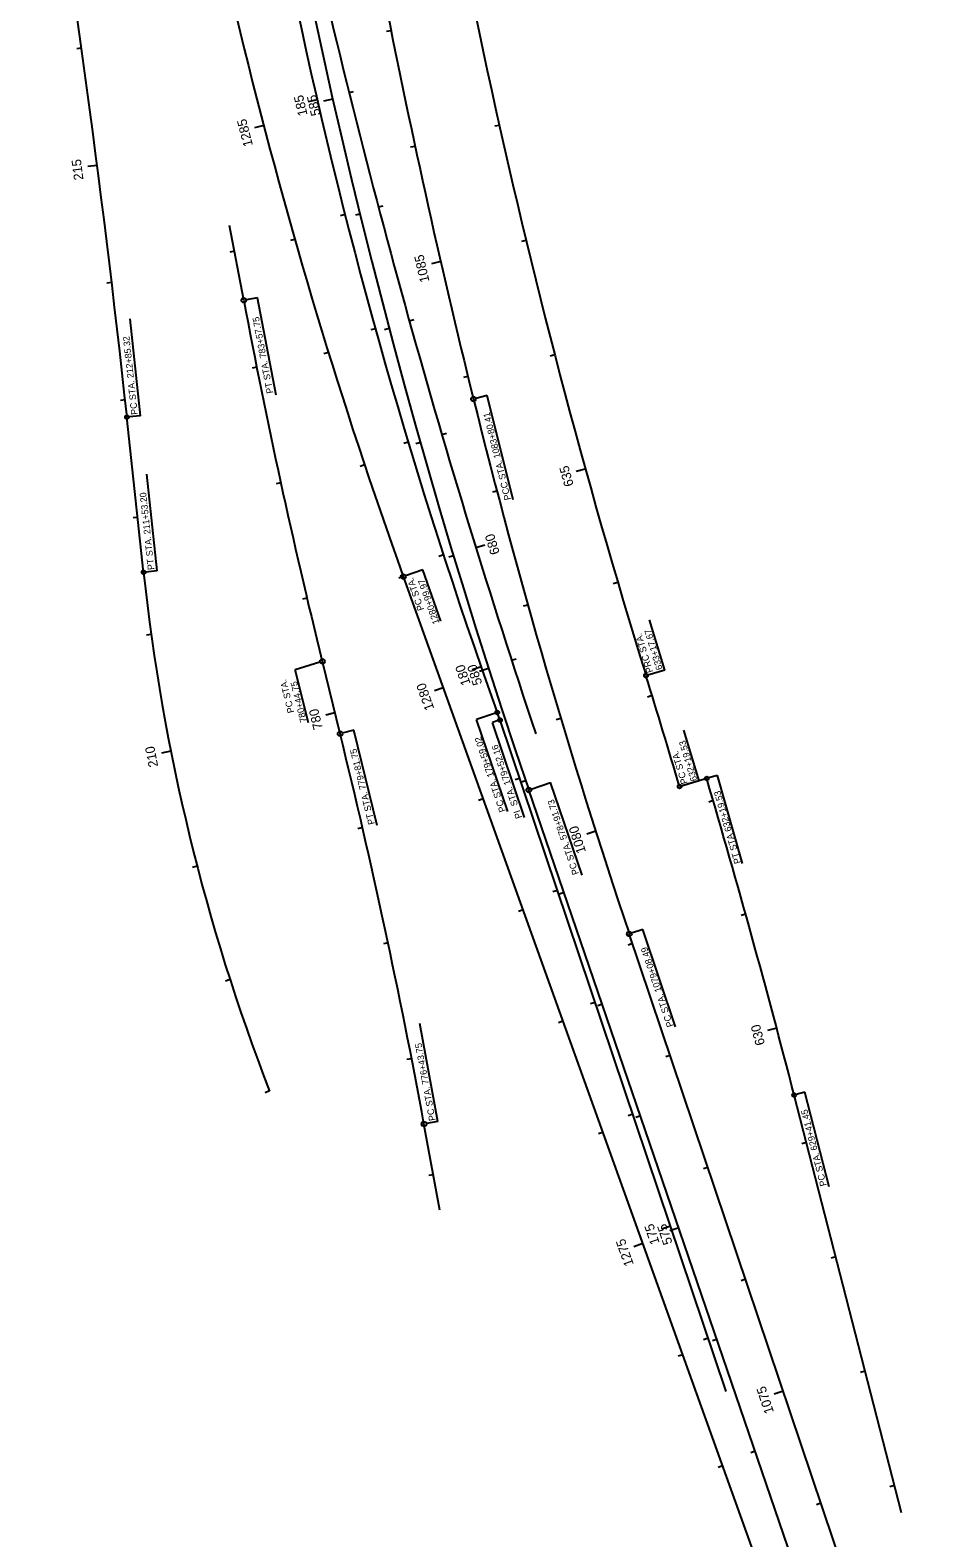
# Model space of a CAD drawing. Extents: x 919451 to 931682, y 583214 to 665619.
# Drawn here: x 928872 to 929643, y 633141 to 634418 of the extents above; entities that cross this region are included whole.
import ezdxf

# ---------------------------------------------------------------- set-up
doc = ezdxf.new("R2010")
doc.units = 0
for name, color, linetype in [('CLConst_dp', 7, 'Continuous'), ('ScratchEle_dp', 7, 'Continuous'), ('StationTicL_dp', 7, 'Continuous'), ('StationTicS_dp', 7, 'Continuous'), ('TextBLStation', 7, 'Continuous')]:
    doc.layers.add(name, color=color, linetype=linetype)

msp = doc.modelspace()

# ---------------------------------------------------------------- linework, layer by layer
at = {"layer": 'CLConst_dp'}
for p, q in [((929052.5, 634189), (929040.6, 634252.2)), ((928967.7, 633958.7), (928953.6, 634090.1)), ((929494.7, 633100.4), (929187.7, 633955.1)), ((929134.1, 633822), (929119.1, 633883.2)), ((929269.6, 633833.6), (929267.3, 633840)), ((929461.1, 633265), (929269.6, 633833.6)), ((929444.7, 633784.1), (929421.7, 633777.3)), ((929643, 632755.1), (929294, 633774.4)), ((929620.6, 632935.5), (929379.1, 633652.5)), ((929609.6, 633162.5), (929518.7, 633516.1)), ((929218.7, 633418.6), (929205.2, 633491.6))]:
    msp.add_line(p, q, dxfattribs=at)
for centre, radius, start, end in [((934714.8, 635630.2), 5729.6, 175.95543, 198.89818), ((935124, 635648.4), 6000, 187.10964, 197.22933), ((933402.4, 635469), 4478.4, 187.8142, 199.7579), ((936244.1, 635835), 7207.6, 188.19915, 193.88471), ((919061.7, 633026.1), 9949, 6.13885, 9.59073), ((936128.2, 636105.4), 7200, 192.63655, 198.49103), ((933581.1, 635389.5), 4583.7, 191.9832, 199.7579), ((934682.4, 635253.2), 5729.6, 190.7042, 193.8342), ((934799.6, 635477.9), 5719.6, 193.8847, 198.6121), ((930687.2, 634143.6), 1729.4, 186.1389, 201.1539), ((922119.5, 631615.5), 7615.4, 16.49098, 17.22933), ((923570.7, 632452), 5729.6, 10.4542, 13.8342), ((922119.5, 631615.5), 7639.4, 14.40537, 16.49098)]:
    msp.add_arc(centre, radius, start, end, dxfattribs=at)
at = {"layer": 'StationTicL_dp'}
for p, q in [((929064.3, 634191.2), (929054.5, 634189.4)), ((929079.9, 634108.8), (929064.3, 634191.2)), ((928965.1, 634091.3), (928956.3, 634173.3)), ((929258.8, 634108.3), (929249.1, 634105.9)), ((929280.6, 634020.1), (929258.8, 634108.3)), ((928965.1, 634091.3), (928955.2, 634090.2)), ((928979.3, 633959.8), (928970.5, 634041.8)), ((928979.3, 633959.8), (928969.3, 633958.7)), ((929204.3, 633960.8), (929189.6, 633955.7)), ((929219.4, 633917.3), (929204.3, 633960.8)), ((929409.1, 633875.9), (929396.2, 633918.5)), ((929117.1, 633882.7), (929096.2, 633876.2)), ((929107.3, 633831.3), (929096.2, 633876.2)), ((929409.1, 633875.9), (929394.7, 633871.6)), ((929265.8, 633839.5), (929249.8, 633834.1)), ((929276.1, 633756.1), (929249.8, 633834.1)), ((929268.1, 633833.1), (929263.3, 633831.5)), ((929290.4, 633751.2), (929263.3, 633831.5)), ((929145.8, 633824.9), (929136, 633822.5)), ((929165.6, 633744.4), (929145.8, 633824.9)), ((929438.2, 633782.1), (929425.2, 633825.1)), ((929295.9, 633775.1), (929312.3, 633780.7)), ((929339.1, 633702.4), (929312.3, 633780.7)), ((929438.2, 633782.1), (929423.2, 633777.7)), ((929453.7, 633786.7), (929446.2, 633784.6)), ((929475.1, 633712.1), (929453.7, 633786.7)), ((929390.5, 633656.3), (929381, 633653.1)), ((929418.3, 633573.8), (929390.5, 633656.3)), ((929217, 633493.8), (929201.7, 633576.7)), ((929527.8, 633518.5), (929520.3, 633516.6)), ((929548.4, 633438.4), (929527.8, 633518.5)), ((929217, 633493.8), (929207.2, 633492))]:
    msp.add_line(p, q, dxfattribs=at)
for centre, radius in [((929052.5, 634189), 2), ((929247.1, 634105.4), 2), ((928953.6, 634090.1), 1.6), ((928967.7, 633958.7), 1.6), ((929187.7, 633955.1), 2), ((929119.1, 633883.2), 2), ((929393.2, 633871.2), 1.6), ((929267.3, 633840), 1.6), ((929269.6, 633833.6), 1.6), ((929134.1, 633822), 2), ((929421.7, 633777.3), 1.6), ((929444.7, 633784.1), 1.6), ((929444.7, 633784.1), 1.6), ((929294, 633774.4), 2), ((929379.1, 633652.5), 2), ((929518.7, 633516.1), 1.6), ((929205.2, 633491.6), 2)]:
    msp.add_circle(centre, radius, dxfattribs=at)
at = {"layer": 'StationTicS_dp'}
for p, q in [((929114.8, 634358.8), (929107, 634357)), ((929127.9, 634359.3), (929120.1, 634357.5)), ((929069.5, 634337.1), (929061.7, 634335.1)), ((928928.4, 634303.2), (928920.4, 634302.2)), ((929219.4, 634221.7), (929211.6, 634219.9)), ((929341.8, 634046.1), (929334.1, 634044)), ((929249.2, 633979.6), (929256.8, 633982)), ((929253.6, 633878.7), (929246, 633876)), ((929259.9, 633877.2), (929252.3, 633874.7)), ((929221.5, 633861), (929214, 633858.3)), ((929129.8, 633839.7), (929122, 633837.8)), ((928990.8, 633807.3), (928983, 633805.7)), ((929350.6, 633739.4), (929343, 633737)), ((929504, 633572.7), (929496.2, 633570.7)), ((929413.9, 633405.1), (929406.3, 633402.5)), ((929420.9, 633403.8), (929413.3, 633401.2)), ((929390.5, 633390.4), (929383, 633387.7)), ((929509.5, 633265.3), (929501.9, 633262.8))]:
    msp.add_line(p, q, dxfattribs=at)
at = {"layer": 'TextBLStation'}
for p, q in [((929177.3, 634417.2), (929173.4, 634416.5)), ((928915, 634402.4), (928911.1, 634401.8)), ((929141.7, 634364.9), (929145.6, 634365.9)), ((929269, 634337.1), (929265.1, 634336.3)), ((929197.7, 634319.3), (929193.8, 634318.5)), ((929166.6, 634268), (929170.5, 634269)), ((929138.4, 634261.6), (929134.5, 634260.6)), ((929150.9, 634261.9), (929147.1, 634261)), ((929095.8, 634240.6), (929092, 634239.5)), ((929291.7, 634239.7), (929287.8, 634238.8)), ((929044.7, 634230.5), (929040.8, 634229.8)), ((928940.7, 634204), (928936.7, 634203.5)), ((929164, 634164.9), (929160.2, 634163.9)), ((929175.7, 634165.1), (929171.8, 634164)), ((929192.8, 634171.5), (929196.6, 634172.6)), ((929124.3, 634144.8), (929120.5, 634143.6)), ((929315.9, 634142.7), (929312.1, 634141.7)), ((929063.6, 634132.3), (929059.6, 634131.5)), ((929242.4, 634124.4), (929238.6, 634123.5)), ((928952, 634104.7), (928948.1, 634104.2)), ((929220.3, 634075.4), (929224.2, 634076.5)), ((929191.8, 634068.9), (929188, 634067.7)), ((929202.1, 634068.6), (929198.2, 634067.5)), ((929154.9, 634049.6), (929151.1, 634048.3)), ((929084, 634034.4), (929080.1, 634033.5)), ((929267, 634027.5), (929263.1, 634026.5)), ((928962.7, 634005.2), (928958.8, 634004.8)), ((929221.7, 633973.4), (929217.9, 633972.2)), ((929230.2, 633972.6), (929226.3, 633971.5)), ((929187.7, 633955.1), (929183.9, 633953.8)), ((929369.4, 633950), (929365.5, 633948.9)), ((929106.1, 633936.9), (929102.2, 633936)), ((929293.2, 633931), (929289.3, 633929.9)), ((928974.2, 633905.9), (928970.3, 633905.4)), ((929279.4, 633884.3), (929283.2, 633885.5)), ((929398.4, 633854.3), (929394.6, 633853.1)), ((929321.1, 633834.9), (929317.2, 633833.8)), ((929286.2, 633784.2), (929282.4, 633782.9)), ((929291.4, 633782.2), (929287.6, 633780.9)), ((929255.3, 633766.9), (929251.5, 633765.5)), ((929450.2, 633765.4), (929446.4, 633764.2)), ((929153.1, 633742.5), (929149.2, 633741.6)), ((929013.1, 633709.8), (929009.2, 633708.8)), ((929318.2, 633689.4), (929314.4, 633688.1)), ((929323.7, 633687.6), (929320, 633686.3)), ((929289.1, 633672.8), (929285.3, 633671.4)), ((929477.7, 633669.2), (929473.9, 633668.1)), ((929174.8, 633644.9), (929170.9, 633644)), ((929381.8, 633644.4), (929378, 633643.1)), ((929041, 633613.8), (929037.2, 633612.6)), ((929350.1, 633594.6), (929346.3, 633593.3)), ((929356.1, 633593), (929352.3, 633591.7)), ((929322.9, 633578.7), (929319.1, 633577.3)), ((929413.8, 633549.6), (929410, 633548.4)), ((929194.7, 633546.9), (929190.8, 633546.1)), ((929074.4, 633519.6), (929070.6, 633518.1)), ((929382, 633499.8), (929378.2, 633498.6)), ((929388.5, 633498.4), (929384.7, 633497.1)), ((929356.7, 633484.5), (929352.9, 633483.2)), ((929529.1, 633475.9), (929525.2, 633474.9)), ((929213.2, 633448.6), (929209.2, 633447.9)), ((929445.7, 633454.9), (929441.9, 633453.6)), ((929553.9, 633379.1), (929550.1, 633378.1)), ((929477.6, 633360.1), (929473.8, 633358.8)), ((929445.8, 633310.3), (929442, 633309)), ((929453.3, 633309.2), (929449.5, 633307.9)), ((929424.3, 633296.3), (929420.6, 633295)), ((929578.8, 633282.2), (929574.9, 633281.2)), ((929485.7, 633214.6), (929481.9, 633213.3)), ((929458.1, 633202.2), (929454.4, 633200.9)), ((929603.7, 633185.4), (929599.8, 633184.4)), ((929541.4, 633170.6), (929537.6, 633169.3))]:
    msp.add_line(p, q, dxfattribs=at)

# ---------------------------------------------------------------- texts
at = {"layer": 'ScratchEle_dp'}
for s, rotation, p in [('185', 102.9956, (929106.6, 634346)), ('585', 102.8155, (929117.6, 634346.1)), ('1285', 104.64, (929060.4, 634320.2)), ('215', 97.3752, (928916.8, 634291.2)), ('1085', 102.9341, (929209.9, 634205.1)), ('635', 105.4882, (929332.1, 634032.5)), ('680', 107.1721, (929269.5, 633975)), ('180', 109.2456, (929244.8, 633864.5)), ('580', 107.8155, (929254.6, 633864.5)), ('1280', 109.7579, (929214, 633843.4)), ('780', 103.8342, (929119.6, 633826.5)), ('210', 101.2146, (928980.1, 633794.5)), ('1080', 107.6955, (929342.5, 633722.1)), ('630', 104.8445, (929494.1, 633559.3)), ('175', 108.6119, (929404.9, 633391)), ('575', 108.8982, (929415.8, 633390.9)), ('1275', 109.7579, (929383, 633372.8)), ('1075', 108.6121, (929501.7, 633247.8))]:
    msp.add_text(s, height=8, rotation=rotation, dxfattribs=at).set_placement(p)
at = {"layer": 'StationTicL_dp'}
for s, rotation, p in [('PT STA. 783+57.75', 100.7042, (929077.6, 634110.6)), ('PC STA. 212+85.32', 96.1389, (928962.8, 634092.4)), ('PCC STA. 1083+80.41', 103.8847, (929279, 634020.5)), ('PT STA. 211+53.20', 96.1389, (928976.9, 633961)), ('PC STA.', 109.118, (929205.4, 633927.3)), ('1280+99.97', 109.118, (929218.3, 633915.9)), ('PRC STA.', 106.7937, (929399.3, 633874.5)), ('633+17.67', 106.7937, (929407.4, 633876.9)), ('PC STA.', 103.8342, (929095.4, 633840.3)), ('780+44.75', 103.8342, (929106, 633832.3)), ('PC STA. 179+59.02', 108.6119, (929274.6, 633756.7)), ('632+19.53', 106.7937, (929436.7, 633782.7)), ('PT STA. 779+81.75', 103.8342, (929163.6, 633745.8)), ('PI  STA. 179+52.16', 108.6119, (929288.4, 633751.2)), ('PC STA.', 106.7937, (929428.6, 633780.3)), ('PC STA. 578+91.73', 108.8982, (929336.6, 633703.7)), ('PT STA 632+19.53', 106.0427, (929473.7, 633712.8)), ('PC STA. 1079+08.49', 108.6121, (929416.6, 633574.7)), ('PC STA. 776+43.75', 100.4542, (929215.1, 633494.8)), ('PC STA. 629+41.45', 104.4054, (929546.4, 633439.7))]:
    msp.add_text(s, height=5.6, rotation=rotation, dxfattribs=at).set_placement(p)

doc.saveas('drawing.dxf')
